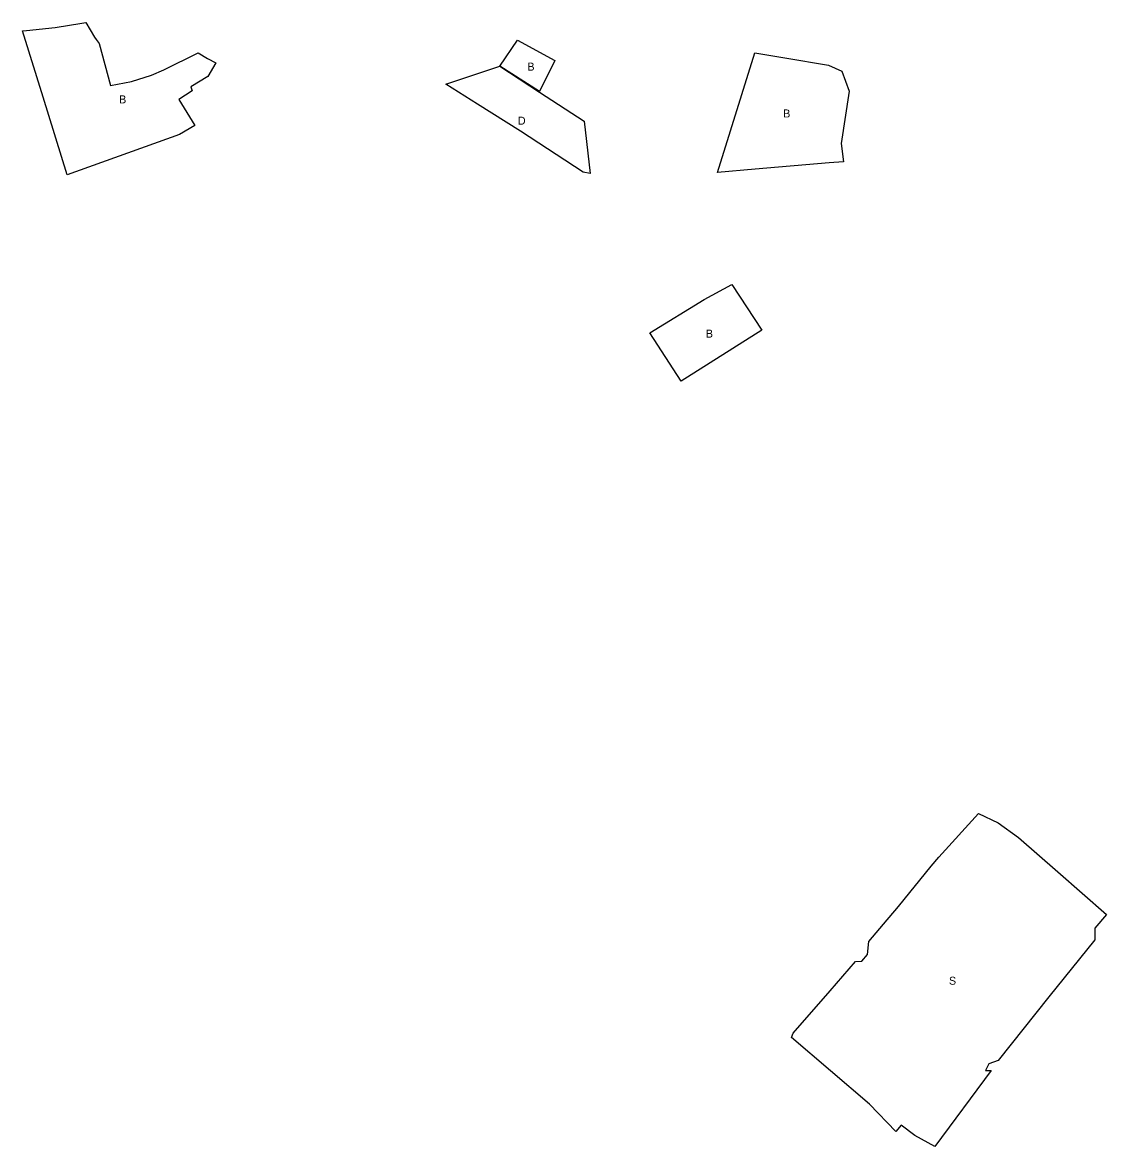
# Model space of a CAD drawing. Extents: x -476493 to -466317, y -1156890 to -1150260.
# Drawn here: x -472103 to -471426, y -1154185 to -1153483 of the extents above; entities that cross this region are included whole.
import ezdxf

# ---------------------------------------------------------------- set-up
doc = ezdxf.new("R2010")
doc.units = 0
for name, color, linetype in [('Vrstva 1', 7, 'Continuous'), ('Vrstva 2', 7, 'Continuous'), ('Vrstva 7', 7, 'Continuous')]:
    doc.layers.add(name, color=color, linetype=linetype)

msp = doc.modelspace()

# ---------------------------------------------------------------- linework, layer by layer
at = {"layer": 'Vrstva 1'}
for points in [[(-472103.11, -1153487.91), (-472100.49, -1153487.65), (-472082.7, -1153485.87), (-472065.99, -1153483.23), (-472063.61, -1153482.72), (-472057.99, -1153491.82), (-472057.06, -1153493.35), (-472055.1, -1153495.9), (-472048.13, -1153522.01), (-472034.9, -1153519.59), (-472022.48, -1153515.68), (-472014.66, -1153512.27), (-471993.23, -1153501.73), (-471987.44, -1153505.13), (-471982.3, -1153508.02), (-471987.31, -1153516.36), (-471997.95, -1153522.99), (-471997.01, -1153525.46), (-472005.43, -1153530.9), (-471995.31, -1153546.97), (-472005.01, -1153552.59), (-472075.128, -1153577.793), (-472090.23, -1153529.33)], [(-471804.738, -1153510.11), (-471793.644, -1153493.747), (-471770.35, -1153506.509), (-471780.031, -1153525.834)], [(-471645.34, -1153501.582), (-471626.74, -1153504.79), (-471599.28, -1153509.37), (-471591.14, -1153513.1), (-471586.54, -1153525.61), (-471591.48, -1153558.36), (-471590.04, -1153569.76), (-471599.01, -1153570.47), (-471645.18, -1153574.33), (-471668.78, -1153576.53)], [(-471711.05, -1153676.5), (-471677.06, -1153655.78), (-471659.87, -1153646.43), (-471640.991, -1153675.01), (-471691.403, -1153706.739)]]:
    msp.add_lwpolyline(points, close=True, dxfattribs=at)
at = {"layer": 'Vrstva 2'}
msp.add_lwpolyline([(-471804.738, -1153510.11), (-471779.981, -1153526.204), (-471752.104, -1153544.327), (-471748.41, -1153577.02), (-471752.72, -1153576.13), (-471791.93, -1153550.64), (-471818.67, -1153533.77), (-471838.573, -1153521.232), (-471828.574, -1153517.945)], close=True, dxfattribs=at)
at = {"layer": 'Vrstva 7'}
msp.add_lwpolyline([(-471505.635, -1153976.73), (-471493.29, -1153982.71), (-471480.55, -1153991.85), (-471455.99, -1154013.35), (-471425.61, -1154039.96), (-471432.98, -1154048.55), (-471432.98, -1154055.72), (-471461.68, -1154091.39), (-471493.43, -1154131.18), (-471499.08, -1154133.14), (-471501.26, -1154137.27), (-471497.78, -1154137.27), (-471533.01, -1154184.84), (-471545.4, -1154177.88), (-471553.88, -1154171.57), (-471557.36, -1154175.49), (-471573.67, -1154158.31), (-471622.54, -1154116.67), (-471621.46, -1154114.06), (-471598.3, -1154087.64), (-471582.42, -1154069.37), (-471578.62, -1154069.04), (-471574.92, -1154064.91), (-471574.16, -1154056.87), (-471564.92, -1154045.885), (-471555.68, -1154034.9), (-471535.24, -1154009.68), (-471530.45, -1154004.13)], close=True, dxfattribs=at)

# ---------------------------------------------------------------- texts
at = {"layer": 'Vrstva 1'}
for s, p in [('B', (-471787.544, -1153512.79)), ('B', (-472042.705, -1153533.256)), ('B', (-471627.66, -1153542.056)), ('D', (-471793.492, -1153546.565)), ('B', (-471676.02, -1153679.584)), ('S', (-471524.075, -1154083.785))]:
    msp.add_text(s, height=5, dxfattribs=at).set_placement(p)

doc.saveas('drawing.dxf')
